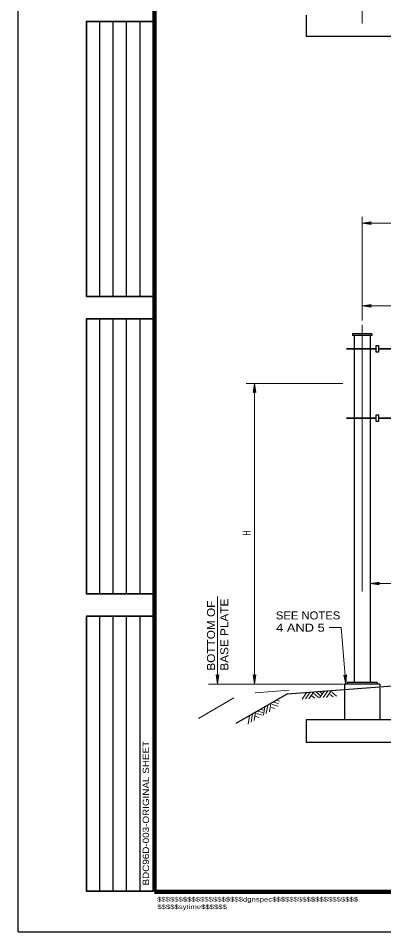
# Model space of a CAD drawing. Extents: x 312601.858 to 312602.699, y 144420.109 to 144420.704.
# Drawn here: x 312601.8578 to 312601.9947, y 144420.1095 to 144420.4517 of the extents above; entities that cross this region are included whole.
import ezdxf
from ezdxf.enums import TextEntityAlignment as Align

# ---------------------------------------------------------------- set-up
doc = ezdxf.new("R2010")
doc.units = 0
doc.header["$LTSCALE"] = 0.0012
doc.linetypes.add('DOT_DASHED', pattern=[7.7, 5, -1.2, 0.3, -1.2])
doc.linetypes.add('LONG_DASHED', pattern=[7.5, 6, -1.5])
for name, color, linetype, lineweight in [('1', 7, 'Continuous', 13), ('39', 7, 'Continuous', 13), ('60', 7, 'Continuous', 25)]:
    doc.layers.add(name, color=color, linetype=linetype, lineweight=lineweight)
doc.layers.add('2', color=7, linetype='Continuous')

msp = doc.modelspace()

# ---------------------------------------------------------------- hatches: boundary and pattern name
at = {"layer": '39'}
for points in [[(312601.9897, 144420.3749), (312601.99, 144420.3744), (312601.9866, 144420.3749), (312601.99, 144420.3754)], [(312601.9897, 144420.344), (312601.99, 144420.3435), (312601.9866, 144420.344), (312601.99, 144420.3445)], [(312601.9897, 144420.344), (312601.99, 144420.3435), (312601.9866, 144420.344), (312601.99, 144420.3445)], [(312601.9463, 144420.3118), (312601.9458, 144420.3115), (312601.9463, 144420.3149), (312601.9468, 144420.3115)], [(312601.9463, 144420.3118), (312601.9458, 144420.3115), (312601.9463, 144420.3149), (312601.9468, 144420.3115)], [(312601.9927, 144420.2399), (312601.993, 144420.2394), (312601.9896, 144420.2399), (312601.993, 144420.2404)], [(312601.9927, 144420.2399), (312601.993, 144420.2394), (312601.9896, 144420.2399), (312601.993, 144420.2404)], [(312601.9324, 144420.2054), (312601.9329, 144420.2057), (312601.9324, 144420.2023), (312601.9319, 144420.2057)], [(312601.9463, 144420.2054), (312601.9468, 144420.2057), (312601.9463, 144420.2023), (312601.9458, 144420.2057)], [(312601.9802, 144420.2054), (312601.9807, 144420.2057), (312601.9805, 144420.2023), (312601.9797, 144420.2056)]]:
    msp.add_hatch(color=256, dxfattribs=at).paths.add_polyline_path(points)

# ---------------------------------------------------------------- linework, layer by layer
at = {"layer": '1'}
for p, q in [((312601.9324, 144420.2351), (312601.9324, 144420.2023)), ((312601.9796, 144420.2023), (312601.929, 144420.2023)), ((312601.9465, 144420.199), (312601.9593, 144420.2)), ((312601.9641, 144420.1966), (312601.9659, 144420.1992)), ((312601.9654, 144420.1967), (312601.9672, 144420.1993)), ((312601.9667, 144420.1968), (312601.9685, 144420.1994)), ((312601.9693, 144420.1994), (312601.9709, 144420.198)), ((312601.9707, 144420.1971), (312601.9725, 144420.1997)), ((312601.9707, 144420.1995), (312601.9715, 144420.1988)), ((312601.972, 144420.1972), (312601.9738, 144420.1998)), ((312601.9733, 144420.1973), (312601.9751, 144420.1999)), ((312601.9753, 144420.1993), (312601.977, 144420.1978)), ((312601.9253, 144420.1894), (312601.9386, 144420.1971)), ((312601.9545, 144420.1962), (312601.9556, 144420.1959)), ((312601.9678, 144420.1979), (312601.9689, 144420.197)), ((312601.9685, 144420.1988), (312601.9703, 144420.1973)), ((312601.9746, 144420.1984), (312601.9757, 144420.1975)), ((312601.9486, 144420.1928), (312601.9497, 144420.1925)), ((312601.9496, 144420.1906), (312601.9501, 144420.1937)), ((312601.9507, 144420.1913), (312601.9513, 144420.1944)), ((312601.9519, 144420.1919), (312601.9524, 144420.195)), ((312601.9526, 144420.1935), (312601.9539, 144420.1931)), ((312601.9529, 144420.1946), (312601.9551, 144420.194)), ((312601.9533, 144420.1955), (312601.9553, 144420.195)), ((312601.9439, 144420.1873), (312601.9444, 144420.1904)), ((312601.945, 144420.188), (312601.9456, 144420.1911)), ((312601.9462, 144420.1886), (312601.9467, 144420.1917)), ((312601.9467, 144420.1901), (312601.9481, 144420.1897)), ((312601.947, 144420.1912), (312601.9492, 144420.1906)), ((312601.9474, 144420.1921), (312601.9494, 144420.1916))]:
    msp.add_line(p, q, dxfattribs=at)
at = {"layer": '1', "lineweight": 25}
msp.add_lwpolyline([(312601.8578, 144420.1095), (312602.6988, 144420.1095), (312602.6988, 144420.7035)], dxfattribs=at)
for points in [[(312601.9919, 144420.3266), (312601.9919, 144420.3291), (312601.9927, 144420.3291), (312601.9927, 144420.3266)], [(312601.9919, 144420.3006), (312601.9919, 144420.3031), (312601.9927, 144420.3031), (312601.9927, 144420.3006)]]:
    msp.add_lwpolyline(points, close=True, dxfattribs=at)
at = {"layer": '39', "lineweight": 25}
for p, q in [((312601.8578, 144420.1095), (312601.8578, 144420.7035)), ((312601.9902, 144420.3335), (312601.983, 144420.3335)), ((312601.983, 144420.3335), (312601.983, 144420.3329)), ((312601.9902, 144420.3329), (312601.983, 144420.3329)), ((312601.9836, 144420.3329), (312601.9836, 144420.2029)), ((312601.9896, 144420.3329), (312601.9896, 144420.2029)), ((312601.9902, 144420.3335), (312601.9902, 144420.3329)), ((312601.9923, 144420.2029), (312601.981, 144420.2029)), ((312601.981, 144420.2029), (312601.981, 144420.2023)), ((312601.9923, 144420.2029), (312601.9923, 144420.2023)), ((312601.98, 144420.2023), (312601.98, 144420.2002)), ((312601.9932, 144420.2023), (312601.98, 144420.2023)), ((312601.9932, 144420.2023), (312601.9932, 144420.2012)), ((312601.9586, 144420.1986), (312601.9393, 144420.1875))]:
    msp.add_line(p, q, dxfattribs=at)
at = {"layer": '39', "lineweight": 158}
for p, q in [((312601.9088, 144420.1247), (312601.9088, 144420.6645)), ((312601.9088, 144420.1245), (312602.6838, 144420.1245))]:
    msp.add_line(p, q, dxfattribs=at)
at = {"layer": '39', "linetype": 'DOT_DASHED'}
for p, q in [((312601.9866, 144420.4888), (312601.9866, 144420.4497)), ((312601.9866, 144420.3369), (312601.9866, 144420.1935)), ((312602.1352, 144420.3149), (312601.9799, 144420.3149))]:
    msp.add_line(p, q, dxfattribs=at)
at = {"layer": '39', "linetype": 'LONG_DASHED', "lineweight": 25}
for p, q in [((312601.9656, 144420.4529), (312601.9656, 144420.4449)), ((312602.0076, 144420.4449), (312601.9656, 144420.4449)), ((312601.98, 144420.1999), (312601.98, 144420.1889)), ((312601.9932, 144420.2009), (312601.9932, 144420.1889)), ((312602.0077, 144420.1889), (312601.9656, 144420.1889)), ((312601.9656, 144420.1889), (312601.9656, 144420.1804)), ((312602.0077, 144420.1804), (312601.9656, 144420.1804))]:
    msp.add_line(p, q, dxfattribs=at)
at = {"layer": '39'}
for p, q in [((312601.9866, 144420.3773), (312601.9866, 144420.3385)), ((312602.1306, 144420.3749), (312601.9866, 144420.3749)), ((312601.9988, 144420.344), (312601.9866, 144420.344)), ((312601.9794, 144420.3149), (312601.9432, 144420.3149)), ((312601.9463, 144420.2023), (312601.9463, 144420.3149)), ((312602.0133, 144420.2399), (312601.9896, 144420.2399)), ((312601.9787, 144420.2235), (312601.9743, 144420.2235)), ((312601.9787, 144420.2235), (312601.9805, 144420.2023))]:
    msp.add_line(p, q, dxfattribs=at)
at = {"layer": '39', "lineweight": 35}
for p, q in [((312601.9919, 144420.3279), (312601.9807, 144420.3279)), ((312602.1306, 144420.3279), (312601.9927, 144420.3279)), ((312601.9807, 144420.3019), (312601.9919, 144420.3019)), ((312601.9927, 144420.3019), (312602.1306, 144420.3019))]:
    msp.add_line(p, q, dxfattribs=at)
at = {"layer": '39'}
for points in [[(312601.9897, 144420.3749), (312601.99, 144420.3744), (312601.9866, 144420.3749), (312601.99, 144420.3754)], [(312601.9897, 144420.344), (312601.99, 144420.3435), (312601.9866, 144420.344), (312601.99, 144420.3445)], [(312601.9897, 144420.344), (312601.99, 144420.3435), (312601.9866, 144420.344), (312601.99, 144420.3445)], [(312601.9463, 144420.3118), (312601.9458, 144420.3115), (312601.9463, 144420.3149), (312601.9468, 144420.3115)], [(312601.9463, 144420.3118), (312601.9458, 144420.3115), (312601.9463, 144420.3149), (312601.9468, 144420.3115)], [(312601.9927, 144420.2399), (312601.993, 144420.2394), (312601.9896, 144420.2399), (312601.993, 144420.2404)], [(312601.9927, 144420.2399), (312601.993, 144420.2394), (312601.9896, 144420.2399), (312601.993, 144420.2404)], [(312601.9324, 144420.2054), (312601.9329, 144420.2057), (312601.9324, 144420.2023), (312601.9319, 144420.2057)], [(312601.9463, 144420.2054), (312601.9468, 144420.2057), (312601.9463, 144420.2023), (312601.9458, 144420.2057)], [(312601.9802, 144420.2054), (312601.9807, 144420.2057), (312601.9805, 144420.2023), (312601.9797, 144420.2056)]]:
    msp.add_lwpolyline(points, close=True, dxfattribs=at)
at = {"layer": '39', "lineweight": 25}
msp.add_lwpolyline([(312601.9586, 144420.1986), (312602.0489, 144420.2055), (312602.1436, 144420.2079)], dxfattribs=at)
at = {"layer": '60'}
for p, q in [((312601.8883, 144420.3475), (312601.8883, 144420.4505)), ((312601.8933, 144420.3475), (312601.8933, 144420.4505)), ((312601.8983, 144420.3475), (312601.8983, 144420.4505)), ((312601.9034, 144420.3475), (312601.9034, 144420.4505)), ((312601.8883, 144420.2361), (312601.8883, 144420.3391)), ((312601.8933, 144420.2361), (312601.8933, 144420.3391)), ((312601.8983, 144420.2361), (312601.8983, 144420.3391)), ((312601.9034, 144420.2361), (312601.9034, 144420.3391)), ((312601.8883, 144420.1247), (312601.8883, 144420.2277)), ((312601.8933, 144420.1247), (312601.8933, 144420.2277)), ((312601.8983, 144420.1247), (312601.8983, 144420.2277)), ((312601.9034, 144420.1247), (312601.9034, 144420.2277))]:
    msp.add_line(p, q, dxfattribs=at)
at = {"layer": '60', "lineweight": 35}
for points in [[(312601.9084, 144420.3475), (312601.8833, 144420.3475), (312601.8833, 144420.4505), (312601.9084, 144420.4505)], [(312601.9084, 144420.2361), (312601.8833, 144420.2361), (312601.8833, 144420.3391), (312601.9084, 144420.3391)], [(312601.9084, 144420.1247), (312601.8833, 144420.1247), (312601.8833, 144420.2277), (312601.9084, 144420.2277)]]:
    msp.add_lwpolyline(points, dxfattribs=at)

# ---------------------------------------------------------------- texts
at = {"layer": '1', "width": 0.6}
msp.add_text('H', height=0.003, rotation=90, dxfattribs=at).set_placement((312601.9449, 144420.25885), align=Align.CENTER)
at = {"layer": '1', "width": 1.1}
for s, p in [('BOTTOM OF', (312601.9315, 144420.2073)), ('BASE PLATE', (312601.9365, 144420.2073))]:
    msp.add_text(s, height=0.003, rotation=90, dxfattribs=at).set_placement(p)
at = {"layer": '1'}
for s, width, p in [('SEE NOTES', 1.05, (312601.9543, 144420.2265)), ('4 AND 5', 1.2, (312601.9544, 144420.2219))]:
    msp.add_text(s, height=0.003, dxfattribs=dict(at, width=width)).set_placement(p)
at = {"layer": '2', "width": 1.15}
msp.add_text('BDC96D-003-ORIGINAL SHEET', height=0.0024, rotation=90, dxfattribs=at).set_placement((312601.9068, 144420.1539), align=Align.CENTER)
at = {"layer": '2', "width": 1.3}
for s, p in [('$$$$$$$$$$$$$$$$$$$$dgnspec$$$$$$$$$$$$$$$$$$$$', (312601.9098, 144420.1208)), ('$$$$$sytime$$$$$$', (312601.9099, 144420.118))]:
    msp.add_text(s, height=0.001664, dxfattribs=at).set_placement(p)

doc.saveas('drawing.dxf')
